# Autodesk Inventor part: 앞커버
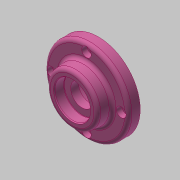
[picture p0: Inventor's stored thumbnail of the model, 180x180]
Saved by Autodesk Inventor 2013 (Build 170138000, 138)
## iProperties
Created: 2017-08
Part Number: 앞커버
Material: 알루미늄 6061
Document SubType Name: Modeling
Designer: mduedu
Density: 1 g/cm^3
Author: mduedu
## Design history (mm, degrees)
sketch "스케치1"
  geometry: C1 r 35 at (0, 0); 1 further point
  constraints: 1 centre point, 1 coincident
  dimensions: "d0" = 70 diameter of C1
extrude "돌출1" new body sketch "스케치1" distance "d1" = 10; taper "d2" = 0 deg
sketch "스케치2"
  geometry: C1 r 22 at (0, 0); 1 further point
  constraints: 1 centre point, 1 coincident
  dimensions: "d3" = 44 diameter of C1
node "작업 평면1"
sketch "스케치3"
  geometry: C1 r 21 at (0, 0); 1 further point
  constraints: 1 centre point, 1 coincident
  dimensions: "d5" = 42 diameter of C1
feature "로프트1" sketch "스케치3" dims "d6" = 0, "d7" = 90 deg, "d8" = 0, "d9" = 90 deg
sketch "스케치4"
  geometry: C1 r 24 at (0, 0); 1 further point
  constraints: 1 centre point, 1 coincident
  dimensions: "d86" = 48 diameter of C1
extrude "돌출2" join sketch "스케치4" distance "d10" = 8; taper "d11" = 0 deg
hole "구멍1" diameter "d14" = 40; stored, may be unused: countersink angle "d18" = 90 deg, drill point angle "d20" = 0 deg; dims "d15" = 6, "d16" = 4, "d17" = 2, "d19" = 12, "d87" = 10, "d88" = 10
hole "구멍2" diameter "d23" = 34; stored, may be unused: countersink angle "d27" = 90 deg, drill point angle "d29" = 0 deg; dims "d21" = 10, "d22" = 10, "d24" = 6, "d25" = 4, "d26" = 2, "d28" = 3
hole "구멍3" diameter "d32" = 19; stored, may be unused: countersink angle "d36" = 90 deg, drill point angle "d38" = 0 deg; dims "d30" = 10, "d31" = 10, "d33" = 6, "d34" = 4, "d35" = 2, "d37" = 3
chamfer "모따기1" distance "d39" = 1; stored, may be unused: second distance "d40" = 2, angle "d41" = 45 deg
sketch "스케치5"
  geometry: C1 r 15 at (0, 0); 1 further point
  constraints: 1 centre point, 1 coincident
  dimensions: "d42" = 30 diameter of C1
extrude "돌출3" cut sketch "스케치5" distance "d43" = 8.3; taper "d44" = 0 deg
chamfer "모따기2" distance "d47" = 0.8; stored, may be unused: second distance "d48" = 2, angle "d49" = 30 deg
fillet "모깎기1" dims "d50" = 0.3
fillet "모깎기2" dims "d51" = 0.3
fillet "모깎기3" dims "d52" = 3
sketch "스케치6" dims "d53" = 58
  geometry: 6 further points
  constraints: 2 vertical alignment, 1 coincident, 7 other
  dimensions: "d56" = 360 deg dimension on point (0, 0) point (0, 29) (derived)
sketch "스케치9" dims "d85" = 58 (derived)
  geometry: 6 further points
  constraints: 1 coincident, 1 vertical alignment, 6 other
hole "구멍6" sketch "스케치9" at (-29, 0), (0, -29), (29, 0), (0, 29) diameter "d72" = 4.5; stored, may be unused: countersink angle "d76" = 90 deg, drill point angle "d78" = 0 deg; dims "d73" = 6, "d74" = 8, "d75" = 4.6, "d77" = 8
fillet "모깎기4" dims "d79" = 3
fillet "모깎기5" dims "d80" = 3
fillet "모깎기6" dims "d81" = 3
node "솔리드1"
other parameters: "d4" = 12
